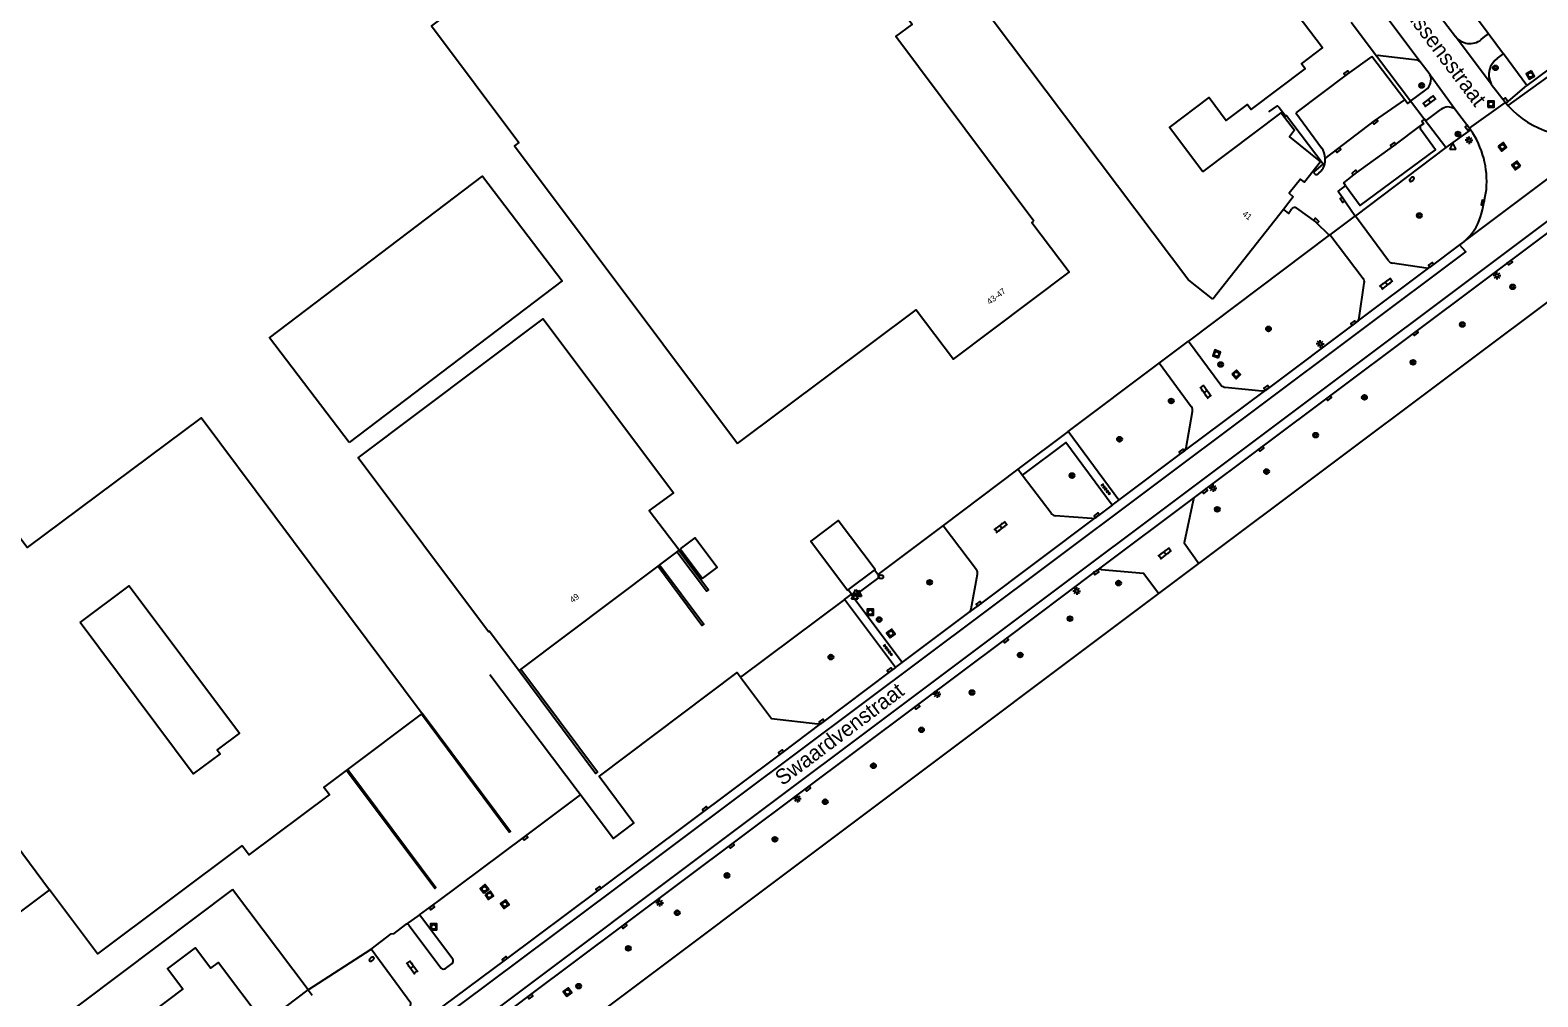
# Model space of a CAD drawing. Extents: x 130998 to 133001, y 398999 to 403002.
# Drawn here: x 131464.1 to 131709.8, y 399814.9 to 399972.4 of the extents above; entities that cross this region are included whole.
import ezdxf

# ---------------------------------------------------------------- set-up
doc = ezdxf.new("R2010")
doc.units = 0
for name, color, linetype in [('gg-afsc-hekwerk', 7, 'Continuous'), ('gg-afsc-muur', 7, 'Continuous'), ('gg-anno-huisnummerreeks BGT', 7, 'Continuous'), ('gg-anno-openbare ruimte label', 7, 'Continuous'), ('gg-bbg-bijgebouw', 7, 'Continuous'), ('gg-bbg-gedigitaliseerde bebouwing', 7, 'Continuous'), ('gg-bbg-gedigitaliseerde bijgebouw', 7, 'Continuous'), ('gg-bbg-hoofdgebouw', 7, 'Continuous'), ('gg-knt-verharding', 7, 'Continuous'), ('gg-knt-verharding nz', 7, 'Continuous'), ('gt-grn-groengrens', 7, 'Continuous'), ('gt-grn-weggrens', 7, 'Continuous'), ('gt-symb-boom', 7, 'Continuous'), ('gt-symb-brandkraan', 7, 'Continuous'), ('gt-symb-klinker verharding', 7, 'Continuous'), ('gt-symb-kolk', 7, 'Continuous'), ('gt-symb-lichtmast', 7, 'Continuous'), ('gt-symb-rioolschacht', 7, 'Continuous'), ('gt-symb-tegel verharding', 7, 'Continuous'), ('gt-symb-waterafsluiter', 7, 'Continuous')]:
    doc.layers.add(name, color=color, linetype=linetype)

# ---------------------------------------------------------------- blocks, each defined once
blk = doc.blocks.new('gt0-LMAST')
at = {"layer": 'gt-symb-lichtmast'}
for p, q in [((-0.18, 0.17), (-0.45, 0.44)), ((-0.01, 0.25), (-0.01, 0.62)), ((0.17, 0.17), (0.44, 0.44)), ((-0.26, 0), (-0.63, 0)), ((-0.18, -0.18), (-0.45, -0.45)), ((-0.01, -0.25), (-0.01, -0.63)), ((0.44, -0.45), (0.17, -0.18)), ((0.24, 0), (0.62, 0))]:
    blk.add_line(p, q, dxfattribs=at)
blk.add_circle((-0.01, 0), 0.25, dxfattribs=at)
blk = doc.blocks.new('gt0-RS')
at = {"layer": 'gt-symb-rioolschacht'}
blk.add_lwpolyline([(-0.5, -0.5), (0.5, -0.5), (0.5, 0.5), (-0.5, 0.5)], close=True, dxfattribs=at)
blk.add_circle((0, 0), 0.375, dxfattribs=at)
blk = doc.blocks.new('gt0-KOLK')
at = {"layer": 'gt-symb-kolk'}
blk.add_lwpolyline([(0, 0), (0.37, 0), (0.37, 0.4), (-0.38, 0.4), (-0.38, 0), (0, 0)], dxfattribs=at)
blk = doc.blocks.new('gt0-BOOM')
at = {"layer": 'gt-symb-boom'}
for radius in [0.4, 0.2]:
    blk.add_circle((0, 0), radius, dxfattribs=at)
blk = doc.blocks.new('gt0-KL1')
at = {"layer": 'gt-symb-klinker verharding'}
for p, q in [((-1.15, 0.3), (1.15, 0.3)), ((-1, -0.3), (-1, 0.3)), ((-0.5, 0.3), (-0.5, 0.45)), ((0, -0.3), (0, 0.3)), ((0.5, 0.3), (0.5, 0.45)), ((1, -0.3), (1, 0.3)), ((-1.15, -0.3), (1.15, -0.3)), ((-0.5, -0.45), (-0.5, -0.3)), ((0.5, -0.45), (0.5, -0.3))]:
    blk.add_line(p, q, dxfattribs=at)
blk = doc.blocks.new('gt0-WAFSL')
at = {"layer": 'gt-symb-waterafsluiter'}
for p, q in [((-0.5, -0.33), (0, 0.67)), ((0, 0.67), (0.5, -0.33)), ((0.5, -0.33), (-0.5, -0.33))]:
    blk.add_line(p, q, dxfattribs=at)
blk = doc.blocks.new('gt0-BR')
at = {"layer": 'gt-symb-brandkraan'}
for centre, radius, start, end in [((-0.24, 0), 0.206, 107.5669, 252.4331), ((0.6, -2.66), 3, 106.892, 107.5669), ((0, -0.69), 0.938, 73.108, 106.892), ((-0.6, -2.66), 3, 72.4331, 73.108), ((0.24, 0), 0.206, 287.567, 72.4331), ((0.6, 2.66), 3, 252.4331, 253.108), ((0, 0.69), 0.938, 253.108, 286.8921), ((-0.6, 2.66), 3, 286.8921, 287.567)]:
    blk.add_arc(centre, radius, start, end, dxfattribs=at)
blk = doc.blocks.new('gt0-TEG1')
at = {"layer": 'gt-symb-tegel verharding'}
for p, q in [((-1.12, 0), (1.12, 0)), ((-0.9, -0.25), (-0.9, 0.25)), ((-0.45, -0.25), (-0.45, 0.25)), ((0, -0.25), (0, 0.25)), ((0.45, -0.25), (0.45, 0.25)), ((0.9, -0.25), (0.9, 0.25))]:
    blk.add_line(p, q, dxfattribs=at)

msp = doc.modelspace()

# ---------------------------------------------------------------- linework, layer by layer
at = {"layer": 'gg-afsc-hekwerk'}
for p, q in [((131680.82, 400000), (131701.68, 399971.91)), ((131683.51, 399968.17), (131679.35, 399973.64)), ((131701.68, 399971.91), (131704.18, 399968.54)), ((131689.05, 399960.86), (131683.51, 399968.17)), ((131708, 399963.4), (131704.18, 399968.54)), ((131713.47, 399967.5), (131708, 399963.4)), ((131691.28, 399957.93), (131689.05, 399960.86)), ((131694.81, 399953.28), (131691.28, 399957.93)), ((131694.81, 399953.28), (131680.05, 399942.19)), ((131680.01, 399942.16), (131675.9, 399939.08)), ((131680.05, 399942.19), (131680.01, 399942.16)), ((131675.8, 399939), (131652.84, 399921.75)), ((131675.9, 399939.08), (131675.8, 399939)), ((131648.06, 399918.16), (131652.84, 399921.75)), ((131633.24, 399907.03), (131648.06, 399918.16)), ((131633.24, 399907.03), (131625.05, 399900.87)), ((131625.05, 399900.87), (131612.88, 399891.73)), ((131612.88, 399891.73), (131602.23, 399883.73)), ((131602.23, 399883.73), (131601.69, 399884.45)), ((131648.01, 399880.63), (131654.56, 399885.54)), ((131503.5, 399772.23), (131648.01, 399880.63)), ((131596.84, 399879.67), (131579.85, 399866.99)), ((131596.84, 399879.67), (131597.89, 399880.46)), ((131553.43, 399848.3), (131539.05, 399867.39)), ((131553.79, 399847.82), (131553.43, 399848.3)), ((131467.32, 399832.34), (131458.31, 399825.62)), ((131497.09, 399832.42), (131465.17, 399808.41)), ((131509.44, 399816.02), (131497.09, 399832.42)), ((131502.25, 399810.62), (131509.44, 399816.02)), ((131509.44, 399816.02), (131510.08, 399815.18))]:
    msp.add_line(p, q, dxfattribs=at)
for points in [[(131654.56, 399885.54), (131797.54, 399992.74), (131803.55, 399997.29)], [(131597.89, 399880.46), (131597.94, 399880.49), (131597.39, 399881.22)]]:
    msp.add_lwpolyline(points, dxfattribs=at)
at = {"layer": 'gg-afsc-muur'}
for points in [[(131569.84, 399887.68), (131574.66, 399881.24), (131574.33, 399881), (131569.5, 399887.42)], [(131566.69, 399885.31), (131573.91, 399875.65), (131573.56, 399875.41), (131566.38, 399885.07)], [(131544.11, 399868.32), (131556.57, 399851.56), (131556.25, 399851.32), (131543.78, 399868.07)], [(131528.02, 399861.02), (131528.08, 399861.07), (131542.39, 399841.83), (131542.21, 399841.72), (131527.9, 399860.94)], [(131515.88, 399851.94), (131530.23, 399832.72), (131530.06, 399832.58), (131515.71, 399851.81)]]:
    msp.add_lwpolyline(points, dxfattribs=at)
at = {"layer": 'gg-bbg-bijgebouw'}
msp.add_line((131597.39, 399881.22), (131601.69, 399884.45), dxfattribs=at)
msp.add_lwpolyline([(131601.69, 399884.45), (131601.79, 399884.53), (131595.79, 399892.5), (131591.31, 399889.13), (131597.31, 399881.16), (131597.39, 399881.22)], dxfattribs=at)
at = {"layer": 'gg-bbg-gedigitaliseerde bebouwing'}
for p in [(131613.69, 399983.8), (131656.83, 399928.57)]:
    msp.add_line(p, (131652.9, 399931.66), dxfattribs=at)
for points in [[(131610.64, 400034.04), (131529.51, 399973.13), (131543.77, 399954.12), (131543.05, 399953.58), (131579.39, 399905.05)], [(131472.28, 399875.91), (131480.29, 399881.89), (131498.24, 399857.86), (131494.63, 399855.16), (131495.11, 399854.52), (131490.71, 399851.23), (131472.28, 399875.91)]]:
    msp.add_lwpolyline(points, dxfattribs=at)
at = {"layer": 'gg-bbg-gedigitaliseerde bijgebouw'}
for points in [[(131516.12, 399905.23), (131503.16, 399922.28), (131537.85, 399948.63), (131550.8, 399931.58), (131516.12, 399905.23)], [(131570.04, 399887.91), (131573.66, 399883.06), (131576.08, 399884.88), (131572.46, 399889.72), (131570.04, 399887.91)]]:
    msp.add_lwpolyline(points, dxfattribs=at)
at = {"layer": 'gg-bbg-hoofdgebouw'}
for p, q in [((131668.32, 399943.19), (131656.83, 399928.57)), ((131569.5, 399887.42), (131566.69, 399885.31)), ((131569.84, 399887.68), (131569.5, 399887.42)), ((131566.38, 399885.07), (131544.11, 399868.32)), ((131566.69, 399885.31), (131566.38, 399885.07)), ((131544.11, 399868.32), (131543.78, 399868.07)), ((131515.88, 399851.94), (131527.9, 399860.94)), ((131527.9, 399860.94), (131528.02, 399861.02)), ((131515.71, 399851.81), (131515.88, 399851.94)), ((131455.18, 399848.61), (131467.32, 399832.34))]:
    msp.add_line(p, q, dxfattribs=at)
for points in [[(131627.67, 399941.28), (131605.17, 399971.36), (131607.83, 399973.36), (131594.37, 399991.29), (131625.33, 400014.47)], [(131655.2, 399949.33), (131649.77, 399956.53), (131656.22, 399961.42), (131658.98, 399957.7), (131662.46, 399960.28), (131663.05, 399959.49), (131671.86, 399966.13), (131671.26, 399966.92), (131674.7, 399969.56), (131669.52, 399976.32), (131672.94, 399978.84), (131675.32, 399975.69), (131676.89, 399976.88)], [(131655.2, 399949.33), (131667.95, 399958.94), (131670.15, 399956.11), (131669.31, 399955.04), (131674.37, 399950.94), (131671.78, 399947.65), (131671.13, 399948.14), (131669.25, 399945.86), (131669.93, 399945.24), (131668.32, 399943.19)], [(131579.39, 399905.05), (131608.5, 399926.85), (131614.56, 399918.8), (131633.42, 399932.99), (131627.35, 399941.04), (131627.67, 399941.28)], [(131543.78, 399868.07), (131538.93, 399874.48), (131538.82, 399874.4), (131517.57, 399902.72), (131547.72, 399925.39), (131568.98, 399897.02), (131565.02, 399894.14), (131569.89, 399887.72), (131569.84, 399887.68)], [(131528.02, 399861.02), (131492, 399909.25), (131463.68, 399888.1), (131460.37, 399892.52), (131435.95, 399874.28)], [(131498.71, 399839.54), (131499.85, 399838.02), (131512.9, 399847.84), (131512, 399849.03), (131515.71, 399851.81)], [(131498.71, 399839.54), (131475.1, 399821.92), (131467.32, 399832.34)], [(131486.25, 399798.61), (131478.85, 399808.45), (131480.67, 399809.82), (131479.96, 399810.76), (131481.19, 399811.69), (131481.88, 399810.77), (131489.04, 399816.13), (131486.51, 399819.48), (131491.07, 399822.91), (131493.6, 399819.55), (131494.83, 399820.48), (131502.25, 399810.62)]]:
    msp.add_lwpolyline(points, dxfattribs=at)
at = {"layer": 'gg-knt-verharding'}
for p, q in [((131681.41, 399991.29), (131696.34, 399971.39)), ((131688.13, 399961.04), (131682.71, 399968.14)), ((131703.23, 399967.83), (131704.18, 399968.54)), ((131692.21, 399965.16), (131690.62, 399967.27)), ((131702.18, 399963.64), (131704.49, 399960.64)), ((131689.05, 399960.86), (131691.55, 399962.68)), ((131698.64, 399956.44), (131704.49, 399960.64)), ((131704.49, 399960.64), (131704.6, 399960.5)), ((131670.33, 399958.95), (131674.55, 399953.27)), ((131696.24, 399959.58), (131698.64, 399956.44)), ((131704.6, 399960.5), (131704.91, 399960.14)), ((131698.64, 399956.44), (131698.82, 399956.2)), ((131674.09, 399949.12), (131674.51, 399949.47)), ((131679.95, 399942.23), (131680.01, 399942.16)), ((131680.05, 399942.19), (131685.44, 399934.86)), ((131681.3, 399931.92), (131675.9, 399939.08)), ((131697.03, 399937.43), (131692.18, 399933.8)), ((131697.76, 399937.98), (131697.03, 399937.43)), ((131680.31, 399924.89), (131692.18, 399933.8)), ((131691.58, 399933.64), (131686.12, 399934.45)), ((131680.68, 399925.53), (131681.51, 399931.19)), ((131680.31, 399924.89), (131665.45, 399913.78)), ((131652.84, 399921.75), (131658.13, 399914.62)), ((131653.32, 399911.03), (131648.06, 399918.16)), ((131658.82, 399914.22), (131664.8, 399913.64)), ((131652.22, 399903.86), (131665.45, 399913.78)), ((131652.46, 399904.36), (131653.52, 399910.27)), ((131641.51, 399895.84), (131633.24, 399907.03)), ((131641.51, 399895.84), (131652.22, 399903.86)), ((131625.76, 399899.93), (131625.05, 399900.87)), ((131630.49, 399893.69), (131625.76, 399899.93)), ((131640.44, 399895.04), (131637.82, 399893.05)), ((131654.01, 399896.42), (131637.99, 399884.44)), ((131640.44, 399895.04), (131641.51, 399895.84)), ((131637.13, 399892.86), (131631.14, 399893.29)), ((131612.88, 399891.73), (131618.31, 399884.51)), ((131617.45, 399878.15), (131618.49, 399883.77)), ((131605.12, 399868.55), (131596.84, 399879.67)), ((131598.15, 399880.1), (131597.89, 399880.46)), ((131606.19, 399869.36), (131598.15, 399880.1)), ((131606.19, 399869.36), (131617.08, 399877.52)), ((131605.12, 399868.55), (131606.19, 399869.36)), ((131532.98, 399821.05), (131527.56, 399828.25)), ((131525.86, 399826.61), (131531.09, 399819.56)), ((131531.8, 399819.54), (131532.88, 399820.35))]:
    msp.add_line(p, q, dxfattribs=at)
for points in [[(131700.57, 399970.87), (131701.43, 399971.61), (131701.68, 399971.91)], [(131690.62, 399967.27), (131690.39, 399967.43), (131690.11, 399967.51), (131684.15, 399968.26), (131683.82, 399968.27), (131683.51, 399968.17)], [(131689.05, 399960.86), (131688.55, 399960.49), (131688.13, 399961.04)], [(131665.93, 399959.1), (131667.38, 399960.1), (131667.66, 399959.81), (131668.71, 399958.4), (131668.83, 399958.51), (131674.8, 399950.61), (131673.24, 399949.28)], [(131691.28, 399957.93), (131691.33, 399957.97), (131691.57, 399957.71), (131693.98, 399959.48)], [(131678.46, 399947.13), (131680.81, 399943.87), (131693.1, 399952.92), (131690.68, 399956.26)], [(131691.28, 399957.93), (131690.9, 399957.61), (131691.14, 399957.17), (131690.72, 399956.88)], [(131729.13, 399952.71), (131701.12, 399931.74), (131664.59, 399904.38), (131654.01, 399896.42)], [(131678.46, 399947.13), (131677.27, 399946.19), (131679.95, 399942.23)], [(131670.45, 399943.43), (131673.55, 399941.21), (131675.8, 399939)], [(131668.32, 399943.19), (131669.14, 399942.56), (131669.7, 399943.35)], [(131640.44, 399895.04), (131632.9, 399905.24), (131625.76, 399899.93)], [(131653.6, 399895.79), (131652.14, 399888.87), (131654.56, 399885.54)], [(131617.08, 399877.52), (131618.82, 399878.8), (131637.82, 399893.05)], [(131527.86, 399801.82), (131529.67, 399803.2), (131545.52, 399815.13), (131560.82, 399826.6), (131608.54, 399862.31), (131622.98, 399873.15), (131637.7, 399884.23), (131637.99, 399884.44)], [(131638.62, 399884.55), (131645.52, 399883.94), (131648.01, 399880.63)], [(131602.23, 399883.73), (131602.4, 399883.25), (131598.15, 399880.1)], [(131579.85, 399866.99), (131579.27, 399867.75), (131556.84, 399850.86), (131562.52, 399843.24), (131559.13, 399840.71), (131553.79, 399847.82)], [(131605.12, 399868.55), (131604.31, 399867.97), (131593.09, 399859.52)], [(131579.85, 399866.99), (131584.94, 399860.26), (131592.5, 399859.37)], [(131525.32, 399808.82), (131541.57, 399820.92), (131556.86, 399832.35), (131586.59, 399854.62), (131593.09, 399859.52)], [(131527.56, 399828.25), (131530.54, 399830.43), (131544.67, 399840.95), (131553.79, 399847.82)], [(131519.68, 399822.67), (131522.98, 399825.17), (131523.43, 399825.25), (131525.34, 399826.71)], [(131525.65, 399809.46), (131526.19, 399813.9), (131519.68, 399822.67)]]:
    msp.add_lwpolyline(points, dxfattribs=at)
for centre, radius, start, end in [((131698.71, 399973.24), 3.01, 217.8766, 308.1035), ((131704.97, 399965.17), 3.18, 123.2062, 208.644), ((131690.32, 399964.33), 2.06, 306.7329, 23.7208), ((131695.18, 399957.94), 1.96, 57.2409, 127.7845), ((131716.04, 399970.05), 14.9, 221.6723, 285.3162), ((131691.09, 399956.54), 0.503, 138.2183, 214.5946), ((131686.71, 399947.8), 14.74, 354.8237, 34.7354), ((131671.96, 399951.4), 3.19, 1.6696, 35.8772), ((131671.95, 399951.39), 3.2, 323.1203, 1.8068), ((131673.7, 399949.39), 0.477, 194.3431, 324.4908), ((131668.09, 399951.18), 33.63, 344.1844, 351.9528), ((131670.13, 399942.87), 0.642, 60.6637, 132.5873), ((131692.23, 399944.57), 8.6, 309.9946, 342.6712), ((131686.27, 399935.45), 1.02, 215.7346, 261.7951), ((131691.63, 399934.67), 1.03, 267.4495, 302.4963), ((131680.58, 399931.33), 0.939, 351.5476, 39.5809), ((131679.55, 399925.75), 1.15, 311.1426, 349.0065), ((131658.89, 399915.13), 0.913, 213.9114, 265.7617), ((131664.95, 399914.54), 0.912, 260.8792, 303.5034), ((131652.53, 399910.42), 1.01, 351.4633, 37.5952), ((131651.68, 399904.43), 0.779, 313.4199, 355.2907), ((131654.68, 399895.54), 1.11, 127.6404, 167.2186), ((131631.27, 399894.22), 0.943, 214.206, 262.0689), ((131637.21, 399893.9), 1.05, 265.6048, 305.3573), ((131617.46, 399883.9), 1.05, 352.9397, 35.6437), ((131638.46, 399883.71), 0.86, 79.1773, 122.4505), ((131616.46, 399878.32), 1.01, 307.6731, 350.7445), ((131592.55, 399860.38), 1.01, 267.2953, 302.1053), ((131525.55, 399826.37), 0.393, 36.3758, 122.0556), ((131532.59, 399820.75), 0.492, 305.8247, 37.7547), ((131531.47, 399820.07), 0.631, 233.5534, 301.9235)]:
    msp.add_arc(centre, radius, start, end, dxfattribs=at)
at = {"layer": 'gg-knt-verharding nz'}
for p, q in [((131690.62, 399967.27), (131680.3, 399981.04)), ((131702.18, 399963.64), (131696.34, 399971.39)), ((131692.21, 399965.16), (131696.24, 399959.58))]:
    msp.add_line(p, q, dxfattribs=at)
for points in [[(131682.71, 399968.14), (131678.73, 399965.26), (131670.33, 399958.95)], [(131675.15, 399951.49), (131683.18, 399957.66), (131688.13, 399961.04)], [(131678.46, 399947.13), (131678.15, 399947.56), (131680.05, 399949.04), (131686.32, 399953.58), (131690.72, 399956.88)], [(131728.21, 399953.93), (131711.9, 399941.71), (131569.53, 399835), (131526.64, 399802.78), (131520.55, 399798.02), (131516.1, 399794.25)], [(131514.11, 399798.95), (131524.18, 399806.1), (131559.42, 399832.43), (131629.64, 399885), (131698.05, 399936.3), (131697.03, 399937.43)]]:
    msp.add_lwpolyline(points, dxfattribs=at)
at = {"layer": 'gt-grn-groengrens'}
for p, q in [((131720.78, 399971.6), (131704.91, 399960.14)), ((131704.6, 399960.5), (131708, 399963.4)), ((131698.82, 399956.2), (131694.81, 399953.28)), ((131527.56, 399828.25), (131525.34, 399826.71)), ((131509.44, 399816.02), (131519.68, 399822.67))]:
    msp.add_line(p, q, dxfattribs=at)
at = {"layer": 'gt-grn-weggrens'}
msp.add_line((131697.76, 399937.98), (131723.22, 399957.13), dxfattribs=at)

# ---------------------------------------------------------------- block references
at = {"layer": 'gt-symb-boom'}
for p in [(131702.87, 399966.28), (131690.86, 399963.41), (131696.76, 399955.5), (131690.47, 399942.22), (131705.68, 399930.6), (131665.89, 399923.74), (131697.48, 399924.46), (131658.1, 399917.94), (131689.45, 399918.3), (131650.05, 399912), (131681.53, 399912.58), (131673.58, 399906.43), (131641.63, 399905.76), (131633.89, 399899.84), (131665.58, 399900.49), (131657.55, 399894.35), (131610.7, 399882.44), (131641.47, 399882.32), (131602.47, 399876.38), (131633.55, 399876.52), (131594.6, 399870.26), (131625.45, 399870.6), (131617.59, 399864.49), (131609.37, 399858.41), (131601.53, 399852.56), (131593.68, 399846.69), (131585.48, 399840.58), (131577.68, 399834.69), (131569.57, 399828.6), (131561.59, 399822.8), (131553.5, 399816.64)]:
    msp.add_blockref('gt0-BOOM', p, dxfattribs=at)
at = {"layer": 'gt-symb-brandkraan'}
for p, rotation in [((131689.24, 399948.12), 39.76890883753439), ((131519.79, 399821.05), -140.80331119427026)]:
    msp.add_blockref('gt0-BR', p, dxfattribs=dict(at, rotation=rotation))
msp.add_blockref('gt0-BR', (131602.75, 399883.34), dxfattribs=at)
at = {"layer": 'gt-symb-klinker verharding'}
for p, rotation in [((131692.12, 399960.84), 36.869897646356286), ((131685.08, 399931.1), 37.1563741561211), ((131655.66, 399913.52), -54.06948106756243), ((131622.29, 399891.45), 36.70953402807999), ((131649.02, 399887.15), 37.1563741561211), ((131526.39, 399819.73), -54.275865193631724)]:
    msp.add_blockref('gt0-KL1', p, dxfattribs=dict(at, rotation=rotation))
at = {"layer": 'gt-symb-kolk'}
for p, rotation in [((131678.73, 399965.26), 35.96415629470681), ((131704.36, 399960.84), -52.109937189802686), ((131683.18, 399957.65), -142.6830255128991), ((131698.5, 399956.62), 127.3625306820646), ((131677.12, 399953.04), -141.9490316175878), ((131686.32, 399953.58), 35.884113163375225), ((131680.05, 399949.04), 37.97050166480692), ((131678.13, 399944.89), 123.7059565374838), ((131701, 399944.27), 78.17329607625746), ((131673.55, 399941.21), -42.1234381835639), ((131692.5, 399934.03), 34.898123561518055), ((131705.09, 399934.72), -143.1759664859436), ((131679.85, 399924.53), 36.74379669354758), ((131689.74, 399923.22), -143.13010235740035), ((131665.7, 399913.97), 37.156374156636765), ((131675.62, 399912.63), -143.13010235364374), ((131651.89, 399903.62), 36.86989764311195), ((131664.59, 399904.38), -143.21030035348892), ((131655.4, 399897.48), -143.08429322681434), ((131638.04, 399893.22), 38.910397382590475), ((131637.7, 399884.23), -146.91369260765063), ((131618.82, 399878.8), 36.42317831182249), ((131622.98, 399873.15), -143.00410224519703), ((131604.31, 399867.97), 35.43780146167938), ((131608.54, 399862.31), -143.13010235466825), ((131593.22, 399859.62), 37.07612031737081), ((131586.59, 399854.62), 36.78969964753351), ((131590.74, 399848.98), -143.1759664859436), ((131574.21, 399845.35), 36.86989764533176), ((131544.67, 399840.95), -143.00410224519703), ((131578.32, 399839.69), -143.21030035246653), ((131556.86, 399832.35), 36.789699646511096), ((131529.48, 399829.63), -143.38348616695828), ((131560.82, 399826.6), -143.21030035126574), ((131541.57, 399820.92), 36.663592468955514), ((131545.52, 399815.13), -143.130102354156)]:
    msp.add_blockref('gt0-KOLK', p, dxfattribs=dict(at, rotation=rotation))
at = {"layer": 'gt-symb-lichtmast'}
for p in [(131698.58, 399954.49), (131703.13, 399932.42), (131674.32, 399921.3), (131656.87, 399897.8), (131634.66, 399881.03), (131611.9, 399864.23), (131589.15, 399847.21), (131566.71, 399830.23)]:
    msp.add_blockref('gt0-LMAST', p, dxfattribs=at)
at = {"layer": 'gt-symb-rioolschacht'}
for p, rotation in [((131708.57, 399965.13), -150.1271789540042), ((131704, 399953.41), -53.37059891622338), ((131706.26, 399950.37), 126.66359246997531), ((131657.45, 399919.66), 68.46463512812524), ((131660.65, 399916.33), -46.215428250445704), ((131604.36, 399874.12), 36.86989764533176), ((131538.15, 399832.49), 37.729269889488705), ((131538.96, 399831.45), -54.40236849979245), ((131541.48, 399830.01), -144.40236850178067), ((131551.67, 399815.68), 36.01052540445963)]:
    msp.add_blockref('gt0-RS', p, dxfattribs=dict(at, rotation=rotation))
for p in [(131702.14, 399960.37), (131601.03, 399877.57), (131529.89, 399826.3)]:
    msp.add_blockref('gt0-RS', p, dxfattribs=at)
at = {"layer": 'gt-symb-tegel verharding'}
for p, rotation in [((131639.4, 399897.62), -52.55716365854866), ((131603.9, 399871.43), -52.557163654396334)]:
    msp.add_blockref('gt0-TEG1', p, dxfattribs=dict(at, rotation=rotation))
at = {"layer": 'gt-symb-waterafsluiter'}
for p in [(131695.94, 399953.28), (131598.48, 399880.05), (131598.64, 399880.61), (131599.11, 399880.49)]:
    msp.add_blockref('gt0-WAFSL', p, dxfattribs=at)

# ---------------------------------------------------------------- texts
at = {"layer": 'gg-anno-huisnummerreeks BGT'}
for s, rotation, p in [('41', 321.8, (131661.54, 399942.3)), ('43-47', 37, (131620.47, 399927.63)), ('49', 37, (131552.52, 399879.03))]:
    msp.add_text(s, height=1, rotation=rotation, dxfattribs=at).set_placement(p)
at = {"layer": 'gg-anno-openbare ruimte label'}
for s, rotation, p in [('Laurent Janssensstraat', 307, (131678.67, 399987.51)), ('Swaardvenstraat', 36.9, (131586.7, 399849.21))]:
    msp.add_text(s, height=2.5, rotation=rotation, dxfattribs=at).set_placement(p)

doc.saveas('drawing.dxf')
